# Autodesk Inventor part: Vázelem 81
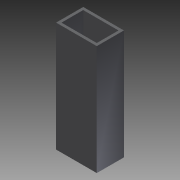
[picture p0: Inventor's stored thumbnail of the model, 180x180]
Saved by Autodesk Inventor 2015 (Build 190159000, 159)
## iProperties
Created: 2013-02
Part Number: Vázelem 81
Material: Generic
Document SubType Name: Modeling
Designer: Marci
Density: 1 g/cm^3
Appearance: Gray
Author: Marci
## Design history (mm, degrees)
sketch "Sketch1"
  geometry: L1 (0, 10)-(15, 10); L2 (15, 10)-(15, -10); L3 (15, -10)-(-15, -10); L4 (-15, -10)-(-15, 10); L5 (-15, 10)-(0, 10); L6 (0, 8)-(13, 8); L7 (13, 8)-(13, -8); L8 (13, -8)-(-13, -8); L9 (-13, -8)-(-13, 8); L10 (-13, 8)-(0, 8); 1 further point
  constraints: 20 end point, 2 collinear, 2 parallel, 4 other
  dimensions: "d0" = 10 distance of point (0, 0) L1.start; "d1" = 15 distance of L1.start L1.end; "d2" = 20 distance of L1.end L2.end; "d3" = 30 distance of L2.end L3.end; "d4" = 2 distance between parallel lines of L4 L9
extrude "Extrusion1" new body sketch "Sketch1" distance "d5" = 81; taper "d6" = 0 deg
body "Solid1"
